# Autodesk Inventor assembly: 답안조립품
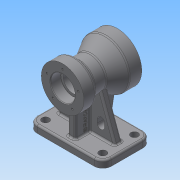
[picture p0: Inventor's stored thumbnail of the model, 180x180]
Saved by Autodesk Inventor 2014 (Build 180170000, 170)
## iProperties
Created: 2015-08
Part Number: 답안조립품
Document SubType Name: Weldment
Designer: SDA24
Weld Material: Welded Aluminum-6061
Author: SDA24
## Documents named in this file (2)
- C:\Users\SDA24\Desktop\450805V1011\답안조립품.iam
- C:\Users\SDA24\Desktop\450805V1011\본체.ipt
